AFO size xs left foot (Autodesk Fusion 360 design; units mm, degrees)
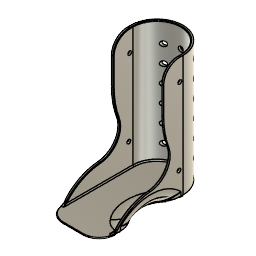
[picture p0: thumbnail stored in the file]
part number: 2025-10-02-12-56-12-317
sketch "Sketch1" plane through (0, 0, 0) normal (0, 0, 1) x axis (1, 0, 0)
  line L1 (-24.25, -78) -> (-24.25, 0)
  line L2 (24.25, -78) -> (-24.25, -78)
  line L3 (24.25, 0) -> (24.25, -78)
  line L4 (-22.25, 0) -> (-22.25, -78)
  line L5 (22.25, 0) -> (22.25, -78)
  line L6 (-22.25, 0) -> (-24.25, 0)
  line L7 (24.25, 0) -> (22.25, 0)
  line L8 (-22.25, -63) -> (-24.25, -63)
  line L9 (-9.25, -78) -> (-9.25, -63)
  line L10 (9.25, -78) -> (9.25, -63)
  line L11 (9.25, -78) -> (-9.25, -78)
  line L12 (30, -63) -> (-11, -63)
  circle C1 centre (0, 0) radius 24.25
  circle C2 centre (0, 0) radius 22.25
  circle C3 centre (-9.25, -63) radius 15
  circle C4 centre (9.25, -63) radius 15
  circle C5 centre (-9.25, -63) radius 13
  circle C6 centre (9.25, -63) radius 13
  point P1 (0, 0)
  point P2 (0, 0)
  point P3 (-24.25, 0)
  point P6 (24.25, 0)
  point P7 (0, 0)
  point P8 (-22.25, 0)
  point P10 (22.25, 0)
  point P11 (22.25, -78)
  point P9 (-22.25, -78)
  point P16 (-24.25, -63)
  point P17 (-22.25, -63)
  point P12 (-9.25, -63)
  point P18 (-9.25, -63)
  point P19 (-9.25, -78)
  point P15 (9.25, -63)
  point P20 (9.25, -63)
  point P21 (9.25, -78)
  coincident P1 P2
  coincident C1 P3
  tangent C1 L1
  vertical L1
  perpendicular L1 L2
  coincident C1 P6
  tangent C1 L3
  perpendicular L2 L3
  coincident P1 P7
  vertical L4
  coincident C2 P8
  vertical L5
  coincident C2 P10
  perpendicular L4 L6
  perpendicular L3 L7
  coincident L2 P11
  coincident L2 P9
  tangent L3 C4
  tangent L1 C3
  tangent L2 C3
  tangent L2 C4
  concentric C3 C5
  tangent L4 C5
  concentric C4 C6
  tangent L5 C6
  coincident C3 P16
  coincident C5 P17
  coincident L4 P17
  perpendicular L4 L8
  coincident P12 P18
  coincident L2 P19
  coincident C3 P19
  perpendicular L2 L9
  coincident P15 P20
  coincident L2 P21
  coincident C4 P21
  perpendicular L2 L10
  perpendicular L3 L12
  dimension "d2" diameter C1 = 48.5 (= "d57 + ( 2 * 2 ) * 1 mm")
  dimension "d4" distance P2 L2 = 78
  dimension "d57" diameter C2 = 44.5
  dimension "d73" diameter C3 = 30
  dimension "d74" diameter C4 = 30
extrude "Extrude1" new body sketch "Sketch1" profile of C1 L1 L3 L4 L5 L6 L7 C3 C4 L8 L12 along normal blind 20
extrude "Extrude2" add sketch "Sketch1" profile of C1 C2 L4 L5 C3 C4 C5 C6 L8 L9 L10 L12 along normal blind 2
extrude "Extrude8" add sketch "Sketch1" profile of L2 C3 C4 L11 along normal blind 2
extrude "Extrude3" add sketch "Sketch1" profile of C1 C2 L6 L7 along normal blind 114.3
work_plane "WorkPlane3" AlongDistance 40
sphere_primitive "SpherePrimitive1" Diameter 70
move_face "MoveFace2"
boundary_fill "BoundaryFill1"
move_face "MoveFace1"
offset_faces "OffsetFaces1" distance 2
shell "Shell4" innerThickness 2
fillet "Fillet10" radius 25
extrude "Extrude14" cut of existing geometry blind -8
fillet "Fillet14" radius 15
fillet "Fillet26" radius 20
fillet "Fillet27" radius 2
work_plane "WorkPlane1" RotateAngle -90
sketch "Sketch2" plane through (24.25, 0, 0) normal (1, 0, 0) x axis (0, 1, 0)
  line L1 (0, 114.3) -> (-18, 114.3)
  line L2 (0, 20) -> (0, 114.3)
  line L3 (-18, 54.3) -> (-18, 114.3)
  line L4 (0, 20) -> (-18, 54.3)
  circle C1 centre (-3, 94.3) radius 1.75
  point P2 (0, 20)
  point P6 (0, 20)
  point P4 (0, 114.3)
  point P7 (0, 114.3)
  point P3 (-18, 114.3)
  point P5 (-18, 54.3)
  point P8 (-3, 94.3)
  horizontal L1
  perpendicular L1 L2
  perpendicular L1 L3
  coincident P2 P6
  coincident P4 P7
  dimension "d25" distance P3 P4 = 18
  dimension "d28" distance P3 P5 = 60
  dimension "d43" diameter C1 = 3.5
  dimension "d45" distance L3 P8 = 15
  dimension "d47" distance L1 P8 = 20
extrude "Extrude11" add sketch "Sketch2" against normal blind 2
mirror "Mirror1" mirrorStitchTolerance 0.1
work_plane "WorkPlane4" AlongDistance 24.25
sketch "Sketch9" plane through (0, 24.25, 0) normal (0, 1, 0) x axis (1, 0, 0)
  circle C1 centre (0, -16) radius 2.25
  circle C2 centre (0, -32) radius 2.25
  circle C3 centre (0, -48) radius 2.25
  circle C4 centre (0, -64) radius 2.25
  circle C5 centre (0, -96) radius 2.25
  circle C6 centre (0, -80) radius 2.25
  point P2 (0, -16)
  point P8 (0, 0)
  point P3 (0, -32)
  point P4 (0, -48)
  point P5 (0, -64)
  point P7 (0, -80)
  point P6 (0, -96)
  dimension "d123" diameter C1 = 4.5
  dimension "d124" diameter C2 = 4.5
  dimension "d125" diameter C3 = 4.5
  dimension "d126" diameter C4 = 4.5
  dimension "d127" diameter C5 = 4.5
  dimension "d128" diameter C6 = 4.5
  dimension "d129" distance P2 P8 = 16
  dimension "d130" distance P2 P3 = 16
  dimension "d131" distance P3 P4 = 16
  dimension "d132" distance P4 P5 = 16 (= "d131")
  dimension "d133" distance P5 P7 = 16 (= "d131")
  dimension "d134" distance P6 P7 = 16 (= "d131")
extrude "Extrude12" cut sketch "Sketch9" against normal blind 80
path_pattern "PathPattern2" PathPatternDelta 69
fillet "Fillet15" radius 45
fillet "Fillet16" radius 1
fillet "Fillet17" radius 15
fillet "Fillet18" radius 80
fillet "Fillet19" radius 20
fillet "Fillet20" radius 5
fillet "Fillet21" radius 0.5
sketch "Sketch10" plane through (0, 0, 0) normal (0, 0, 1) x axis (1, 0, 0)
hole "Hole3" HoleDepth 175 HoleDiameter 3.5 TipAngle 118
fillet "Fillet28" radius 2
fillet "Fillet29" radius 0.5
